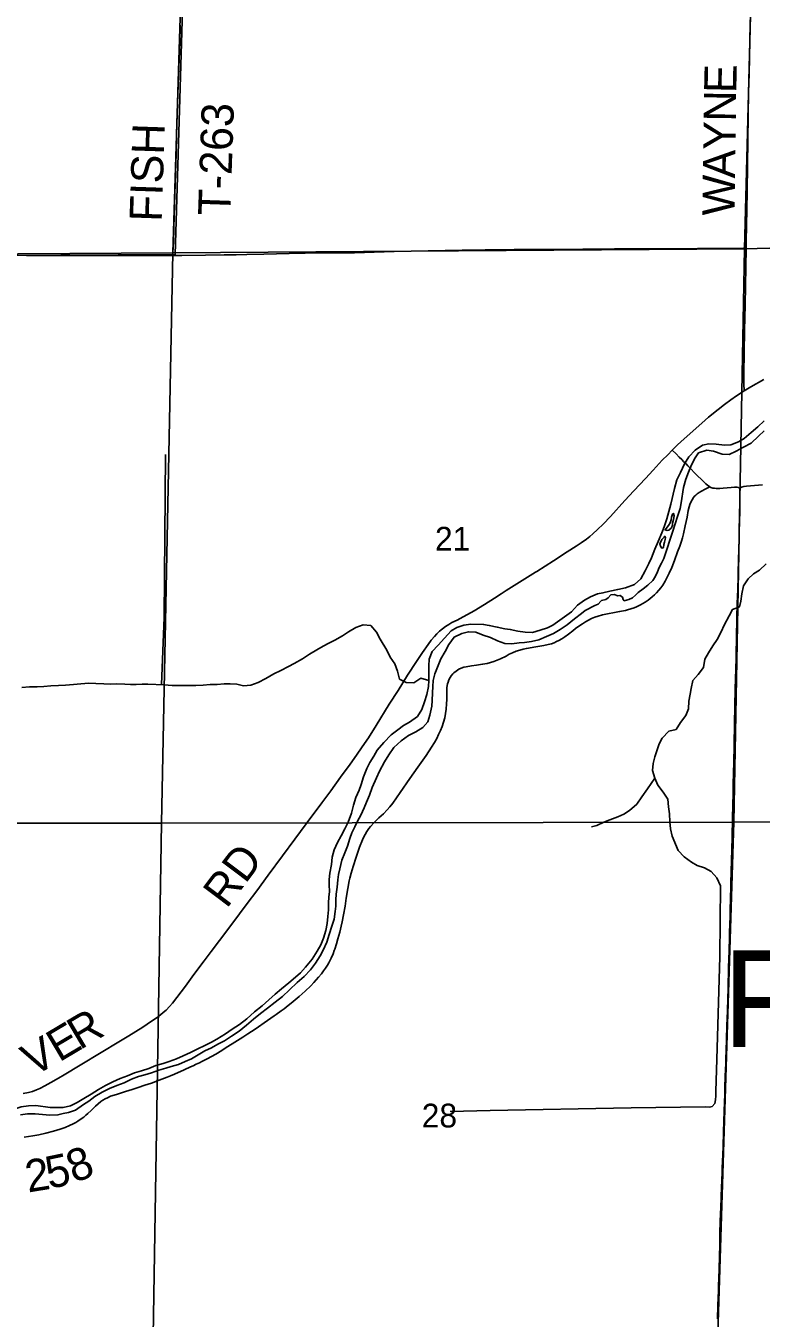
# Model space of a CAD drawing. Extents: x 1443599 to 1910620, y 1028088 to 1361369.
# Drawn here: x 1694297 to 1701141, y 1224516 to 1236539 of the extents above; entities that cross this region are included whole.
import ezdxf

# ---------------------------------------------------------------- set-up
doc = ezdxf.new("R2010")
doc.units = 0
for name, color, linetype in [('GM_X_County_Road', 7, 'Continuous'), ('GM_X_County_Road_Text', 7, 'Continuous'), ('GM_X_Major_River', 7, 'Continuous'), ('GM_X_Minor_River', 7, 'Continuous'), ('GM_X_Section', 7, 'Continuous'), ('GM_X_Section_Text', 7, 'Continuous'), ('GM_X_Township', 7, 'Continuous'), ('GM_X_Township_Road', 7, 'Continuous'), ('GM_X_Township_Road_Text', 7, 'Continuous'), ('GM_X_Township_Text', 7, 'Continuous')]:
    doc.layers.add(name, color=color, linetype=linetype)

msp = doc.modelspace()

# ---------------------------------------------------------------- linework, layer by layer
at = {"layer": 'GM_X_County_Road'}
for points in [[(1700984, 1233144), (1701044, 1233180), (1701165, 1233249)], [(1700314, 1232591), (1700364, 1232642), (1700424, 1232697), (1700590, 1232844), (1700652, 1232898), (1700741, 1232971), (1700799, 1233016), (1700858, 1233060), (1700912, 1233097), (1700974, 1233137), (1700984, 1233144)], [(1694273, 1226605), (1694321, 1226615), (1694359, 1226625), (1694395, 1226639), (1694428, 1226653), (1694475, 1226677), (1694529, 1226707), (1694600, 1226749), (1694653, 1226780), (1694803, 1226870), (1694997, 1226986), (1695162, 1227087), (1695255, 1227143), (1695386, 1227224), (1695468, 1227278), (1695520, 1227313), (1695551, 1227337), (1695576, 1227358), (1695602, 1227382), (1695634, 1227415), (1695662, 1227447), (1695702, 1227498), (1695782, 1227606), (1695860, 1227712), (1695958, 1227840), (1696023, 1227927), (1696101, 1228028), (1696225, 1228194), (1696287, 1228278), (1696358, 1228373), (1696446, 1228492), (1696554, 1228636), (1696686, 1228816), (1696802, 1228971), (1696907, 1229114), (1697052, 1229309), (1697136, 1229423), (1697227, 1229548), (1697316, 1229669), (1697376, 1229755), (1697429, 1229831), (1697485, 1229915), (1697559, 1230031), (1697680, 1230227), (1697762, 1230357), (1697849, 1230497), (1697933, 1230626), (1697988, 1230708), (1698041, 1230783), (1698071, 1230823), (1698100, 1230859), (1698123, 1230883), (1698146, 1230906), (1698174, 1230929), (1698203, 1230951), (1698234, 1230971), (1698263, 1230987), (1698312, 1231011), (1698369, 1231040), (1698409, 1231062), (1698471, 1231098), (1698566, 1231157), (1698658, 1231215), (1698721, 1231255), (1698769, 1231285), (1699041, 1231456), (1699052, 1231463), (1699207, 1231562), (1699337, 1231645), (1699420, 1231699), (1699466, 1231729), (1699517, 1231765), (1699545, 1231787), (1699575, 1231812), (1699619, 1231852), (1699670, 1231903), (1699738, 1231974), (1699873, 1232122), (1699957, 1232213), (1700065, 1232329), (1700136, 1232406), (1700221, 1232497), (1700272, 1232549), (1700314, 1232591)], [(1700663, 1232251), (1700659, 1232253), (1700645, 1232262), (1700626, 1232278), (1700585, 1232318), (1700550, 1232353), (1700459, 1232446), (1700442, 1232464), (1700419, 1232486), (1700402, 1232504), (1700378, 1232527), (1700350, 1232556), (1700314, 1232591)], [(1700939, 1232235), (1700931, 1232243), (1700917, 1232246), (1700910, 1232247), (1700894, 1232247), (1700862, 1232245), (1700789, 1232238), (1700756, 1232236), (1700723, 1232236), (1700706, 1232237), (1700690, 1232239), (1700674, 1232245), (1700663, 1232251)], [(1700734, 1224510), (1700738, 1224633), (1700743, 1224772), (1700744, 1224830), (1700746, 1224879), (1700752, 1225084), (1700755, 1225207), (1700758, 1225313), (1700761, 1225412), (1700764, 1225494), (1700766, 1225543), (1700773, 1225740), (1700775, 1225789), (1700777, 1225879), (1700779, 1225920), (1700781, 1225970), (1700787, 1226109), (1700791, 1226248), (1700794, 1226347), (1700797, 1226437), (1700800, 1226527), (1700802, 1226593), (1700803, 1226668), (1700804, 1226703), (1700806, 1226725), (1700806, 1226767), (1700809, 1226825), (1700812, 1226885), (1700813, 1226923), (1700819, 1227103), (1700823, 1227243), (1700824, 1227300), (1700827, 1227382), (1700833, 1227587), (1700838, 1227776), (1700840, 1227858), (1700842, 1227932), (1700846, 1228063), (1700847, 1228096), (1700850, 1228194), (1700852, 1228243), (1700853, 1228309), (1700857, 1228424), (1700859, 1228530), (1700860, 1228563), (1700863, 1228670), (1700867, 1228875), (1700870, 1228990), (1700874, 1229170), (1700880, 1229400), (1700881, 1229474), (1700884, 1229597), (1700886, 1229679), (1700889, 1229851), (1700894, 1230048), (1700900, 1230368), (1700905, 1230557), (1700908, 1230656), (1700909, 1230697), (1700910, 1230754), (1700911, 1230787), (1700912, 1230860), (1700916, 1231016), (1700919, 1231180), (1700920, 1231213), (1700923, 1231312), (1700926, 1231402), (1700928, 1231459), (1700930, 1231566), (1700933, 1231673), (1700935, 1231763), (1700937, 1231837), (1700938, 1231886), (1700939, 1231935), (1700942, 1232018), (1700944, 1232111), (1700944, 1232146), (1700944, 1232210), (1700943, 1232224), (1700939, 1232235)]]:
    msp.add_lwpolyline(points, dxfattribs=at)
at = {"layer": 'GM_X_Major_River'}
for p, q in [((1700317, 1231893), (1700317, 1231913)), ((1700217, 1231759), (1700202, 1231726))]:
    msp.add_line(p, q, dxfattribs=at)
for points in [[(1701168, 1232864), (1701111, 1232810), (1701048, 1232757), (1700982, 1232701), (1700930, 1232668), (1700859, 1232641), (1700799, 1232637), (1700723, 1232647), (1700653, 1232650), (1700595, 1232638), (1700526, 1232591), (1700468, 1232531), (1700427, 1232464), (1700389, 1232384), (1700357, 1232317), (1700335, 1232235), (1700299, 1232089), (1700283, 1232021), (1700264, 1231952), (1700238, 1231877), (1700217, 1231821), (1700183, 1231742), (1700151, 1231669), (1700121, 1231591), (1700096, 1231538), (1700062, 1231468), (1700020, 1231395), (1699961, 1231341), (1699878, 1231311), (1699806, 1231296), (1699733, 1231280), (1699669, 1231264), (1699619, 1231255), (1699552, 1231226), (1699497, 1231196), (1699432, 1231149), (1699377, 1231088), (1699202, 1230964)], [(1700263, 1231668), (1700293, 1231765), (1700319, 1231837), (1700341, 1231905), (1700363, 1231974), (1700386, 1232050), (1700398, 1232102), (1700417, 1232245), (1700441, 1232323), (1700465, 1232386), (1700492, 1232456), (1700526, 1232519), (1700559, 1232567), (1700634, 1232593), (1700699, 1232581), (1700777, 1232553), (1700843, 1232552), (1700907, 1232582), (1700976, 1232619), (1701047, 1232657), (1701115, 1232723), (1701168, 1232770)], [(1700317, 1231913), (1700324, 1231945), (1700333, 1231981), (1700325, 1232003), (1700315, 1231997), (1700308, 1231967), (1700302, 1231942), (1700293, 1231916), (1700279, 1231892), (1700247, 1231849), (1700265, 1231844), (1700283, 1231848), (1700306, 1231869), (1700317, 1231893)], [(1700202, 1231726), (1700198, 1231718), (1700206, 1231693), (1700217, 1231679), (1700227, 1231683), (1700231, 1231685), (1700236, 1231715), (1700241, 1231735), (1700249, 1231760), (1700252, 1231780), (1700244, 1231791), (1700238, 1231783), (1700217, 1231759)], [(1699334, 1230966), (1699405, 1231021), (1699468, 1231072), (1699503, 1231101), (1699594, 1231145), (1699625, 1231160), (1699649, 1231188), (1699655, 1231192), (1699696, 1231203), (1699718, 1231218), (1699741, 1231244), (1699777, 1231249), (1699804, 1231236), (1699828, 1231240), (1699850, 1231223), (1699858, 1231203), (1699867, 1231191), (1699911, 1231202), (1699944, 1231219), (1699972, 1231242), (1699995, 1231266), (1700044, 1231301), (1700087, 1231334), (1700132, 1231379), (1700155, 1231414), (1700176, 1231458), (1700191, 1231499), (1700214, 1231541), (1700235, 1231584), (1700263, 1231668)], [(1694246, 1226407), (1694314, 1226418), (1694384, 1226417), (1694452, 1226410), (1694520, 1226405), (1694595, 1226407), (1694645, 1226419), (1694695, 1226428), (1694760, 1226451), (1694833, 1226503), (1694882, 1226534), (1694939, 1226579), (1695006, 1226619), (1695076, 1226651), (1695144, 1226680), (1695211, 1226705), (1695280, 1226738), (1695346, 1226765), (1695406, 1226780), (1695467, 1226797), (1695534, 1226824), (1695600, 1226843), (1695650, 1226858), (1695719, 1226877), (1695780, 1226905), (1695840, 1226929), (1695901, 1226965), (1695963, 1227002), (1696024, 1227031), (1696085, 1227064), (1696147, 1227095), (1696212, 1227138), (1696284, 1227185), (1696350, 1227242), (1696415, 1227296), (1696480, 1227351), (1696545, 1227400), (1696618, 1227457), (1696685, 1227508), (1696752, 1227571), (1696824, 1227638), (1696889, 1227695), (1696946, 1227756), (1696993, 1227820), (1697036, 1227887), (1697064, 1227941), (1697098, 1228013), (1697121, 1228085), (1697145, 1228164), (1697166, 1228228), (1697177, 1228300), (1697182, 1228350), (1697183, 1228408), (1697185, 1228459), (1697196, 1228527), (1697201, 1228593), (1697206, 1228643), (1697221, 1228697), (1697238, 1228777), (1697266, 1228844), (1697291, 1228906), (1697314, 1228978), (1697331, 1229030), (1697358, 1229087), (1697385, 1229141), (1697415, 1229195), (1697445, 1229265), (1697467, 1229316), (1697497, 1229382), (1697522, 1229454), (1697562, 1229544), (1697590, 1229605), (1697634, 1229693), (1697675, 1229758), (1697722, 1229824), (1697791, 1229887), (1697858, 1229938), (1697927, 1229971), (1697991, 1230011), (1698038, 1230063), (1698058, 1230127), (1698075, 1230211), (1698080, 1230263), (1698083, 1230333), (1698084, 1230394), (1698089, 1230448), (1698104, 1230509), (1698160, 1230651), (1698199, 1230719), (1698234, 1230784), (1698283, 1230852), (1698354, 1230887), (1698417, 1230902), (1698485, 1230899), (1698555, 1230869)], [(1699202, 1230964), (1699151, 1230940), (1699085, 1230917), (1699014, 1230896), (1698946, 1230897), (1698876, 1230909), (1698806, 1230924), (1698756, 1230929), (1698684, 1230946), (1698610, 1230961), (1698558, 1230970), (1698440, 1230972), (1698375, 1230963), (1698309, 1230943), (1698256, 1230910), (1698195, 1230843), (1698134, 1230778), (1698079, 1230718), (1698050, 1230646), (1698049, 1230585), (1698048, 1230516), (1698048, 1230449), (1698044, 1230392), (1698029, 1230318), (1698009, 1230250), (1697984, 1230179), (1697941, 1230115), (1697868, 1230062), (1697811, 1230029), (1697759, 1229990), (1697698, 1229944), (1697629, 1229873), (1697567, 1229800), (1697536, 1229746), (1697499, 1229685), (1697472, 1229629), (1697441, 1229553), (1697418, 1229482), (1697401, 1229428), (1697370, 1229360), (1697347, 1229290), (1697327, 1229214), (1697296, 1229131), (1697265, 1229067), (1697232, 1229003), (1697199, 1228940), (1697166, 1228874), (1697147, 1228805), (1697142, 1228738), (1697126, 1228656), (1697121, 1228597), (1697119, 1228546), (1697122, 1228484), (1697117, 1228434), (1697114, 1228381), (1697115, 1228315), (1697108, 1228253), (1697103, 1228187), (1697088, 1228121), (1697069, 1228051), (1697044, 1227990), (1697009, 1227930), (1696963, 1227856), (1696900, 1227781), (1696855, 1227730), (1696786, 1227669), (1696744, 1227636), (1696678, 1227581), (1696619, 1227531), (1696558, 1227478), (1696497, 1227421), (1696426, 1227366), (1696355, 1227302), (1696286, 1227249), (1696219, 1227204), (1696156, 1227161), (1696075, 1227112), (1696025, 1227085), (1695962, 1227054), (1695898, 1227021), (1695829, 1226988), (1695760, 1226957), (1695698, 1226928), (1695631, 1226905), (1695575, 1226885), (1695506, 1226867), (1695442, 1226839), (1695375, 1226818), (1695307, 1226799), (1695242, 1226770), (1695175, 1226745), (1695107, 1226716), (1695040, 1226681), (1694973, 1226644), (1694906, 1226601), (1694836, 1226560), (1694775, 1226521), (1694712, 1226491), (1694644, 1226477), (1694576, 1226475), (1694523, 1226475)], [(1698555, 1230869), (1698622, 1230848), (1698688, 1230817), (1698754, 1230794), (1698822, 1230790), (1698888, 1230798), (1698939, 1230803), (1699005, 1230812), (1699073, 1230827), (1699142, 1230858), (1699207, 1230887), (1699271, 1230924), (1699334, 1230966)], [(1694523, 1226475), (1694389, 1226495), (1694321, 1226490), (1694253, 1226481), (1694188, 1226460), (1694124, 1226429), (1694053, 1226396), (1693972, 1226365), (1693913, 1226340), (1693831, 1226313)]]:
    msp.add_lwpolyline(points, dxfattribs=at)
at = {"layer": 'GM_X_Minor_River'}
for points in [[(1695584, 1231034), (1695598, 1232550)], [(1701189, 1231533), (1701126, 1231475), (1701071, 1231442), (1701020, 1231393), (1700976, 1231328), (1700961, 1231254), (1700951, 1231188), (1700940, 1231135), (1700875, 1231110), (1700842, 1231051), (1700798, 1230962)], [(1695560, 1230410), (1695584, 1231034)], [(1698048, 1230449), (1697975, 1230470), (1697908, 1230428), (1697837, 1230430), (1697776, 1230462), (1697756, 1230535), (1697730, 1230604), (1697688, 1230667), (1697658, 1230732), (1697596, 1230834), (1697560, 1230899), (1697508, 1230961), (1697438, 1230965), (1697369, 1230943), (1697299, 1230901), (1697244, 1230864), (1697173, 1230824), (1697116, 1230796), (1697065, 1230767), (1697005, 1230733), (1696938, 1230695), (1696871, 1230651), (1696793, 1230607), (1696742, 1230578), (1696671, 1230542), (1696606, 1230510), (1696532, 1230466), (1696461, 1230430), (1696392, 1230404), (1696324, 1230400), (1696260, 1230414), (1696198, 1230417), (1696144, 1230417), (1696077, 1230411), (1696013, 1230411), (1695947, 1230405), (1695878, 1230403), (1695800, 1230403), (1695724, 1230401), (1695660, 1230403), (1695586, 1230409), (1695431, 1230414), (1695381, 1230413), (1695325, 1230411), (1695271, 1230410), (1695217, 1230414), (1695143, 1230416), (1695082, 1230414), (1695024, 1230417), (1694948, 1230420), (1694882, 1230424), (1694810, 1230418), (1694741, 1230412), (1694667, 1230406), (1694602, 1230402), (1694530, 1230398), (1694466, 1230394), (1694403, 1230389), (1694331, 1230389), (1694261, 1230383)], [(1700798, 1230962), (1700770, 1230900), (1700732, 1230831), (1700692, 1230772), (1700650, 1230707), (1700618, 1230646), (1700604, 1230570), (1700556, 1230503), (1700506, 1230447), (1700490, 1230375), (1700479, 1230321), (1700469, 1230257), (1700465, 1230185), (1700439, 1230124), (1700391, 1230059), (1700349, 1229992), (1700282, 1229976), (1700220, 1229913), (1700192, 1229860), (1700173, 1229804), (1700153, 1229737), (1700137, 1229675), (1700131, 1229611), (1700153, 1229540), (1700179, 1229475), (1700230, 1229410), (1700274, 1229344), (1700278, 1229274), (1700288, 1229209), (1700292, 1229135), (1700296, 1229067), (1700314, 1229000), (1700370, 1228866), (1700423, 1228808), (1700494, 1228758), (1700545, 1228728), (1700615, 1228706), (1700676, 1228670), (1700730, 1228611), (1700762, 1228537)], [(1700153, 1229540), (1700082, 1229440), (1700030, 1229367), (1699984, 1229298), (1699916, 1229238), (1699863, 1229206), (1699808, 1229179), (1699733, 1229151), (1699678, 1229131), (1699613, 1229100), (1699562, 1229086)], [(1700762, 1228537), (1700755, 1227880), (1700728, 1226922), (1700719, 1226629), (1700720, 1226585), (1700715, 1226547), (1700710, 1226513), (1700685, 1226486), (1700661, 1226480), (1700621, 1226483), (1699930, 1226473), (1698619, 1226449), (1698248, 1226438)]]:
    msp.add_lwpolyline(points, dxfattribs=at)
at = {"layer": 'GM_X_Section'}
for points in [[(1695829, 1239703), (1701124, 1239772), (1700987, 1234465), (1695666, 1234426)], [(1701124, 1239772), (1706425, 1239788), (1706263, 1234605), (1700987, 1234465)], [(1695829, 1239703), (1695666, 1234426), (1690385, 1234393), (1690543, 1239680)], [(1706263, 1234605), (1706163, 1229142), (1700887, 1229130), (1700987, 1234465)], [(1690385, 1234393), (1695666, 1234426), (1695560, 1229121), (1690253, 1229120)], [(1700987, 1234465), (1700887, 1229130), (1695560, 1229121), (1695666, 1234426)], [(1690253, 1229120), (1695560, 1229121), (1695473, 1223777), (1690115, 1223779)], [(1695560, 1229121), (1700887, 1229130), (1700722, 1223879), (1695473, 1223777)], [(1700887, 1229130), (1706163, 1229142), (1706163, 1229120), (1706044, 1223810), (1700722, 1223879)]]:
    msp.add_lwpolyline(points, close=True, dxfattribs=at)
at = {"layer": 'GM_X_Township'}
for points in [[(1691028, 1266317), (1696325, 1266276), (1696324, 1260894), (1696308, 1259201), (1696305, 1258547), (1696301, 1258173), (1696288, 1257097), (1696269, 1255587), (1696154, 1250250), (1695980, 1244960), (1695885, 1241542), (1695846, 1239693), (1695686, 1234412), (1693554, 1234401)], [(1693554, 1234401), (1695686, 1234412), (1695846, 1239693)]]:
    msp.add_lwpolyline(points, dxfattribs=at)
at = {"layer": 'GM_X_Township_Road'}
for points in [[(1701001, 1234470), (1701003, 1234534), (1701007, 1234830), (1701010, 1235002), (1701016, 1235478), (1701023, 1235922), (1701028, 1236094), (1701040, 1236554), (1701047, 1236816), (1701057, 1237243), (1701068, 1237785), (1701078, 1238302), (1701081, 1238491), (1701086, 1238737), (1701091, 1239025), (1701094, 1239140), (1701097, 1239255), (1701099, 1239386), (1701101, 1239493), (1701103, 1239608), (1701107, 1239722), (1701107, 1239739), (1701108, 1239773)], [(1695664, 1234402), (1695665, 1234431), (1695670, 1234529), (1695678, 1234776), (1695691, 1235170), (1695695, 1235350), (1695700, 1235531), (1695707, 1235728), (1695719, 1236073), (1695726, 1236303), (1695730, 1236400), (1695731, 1236431), (1695733, 1236496), (1695735, 1236545)], [(1693579, 1234407), (1693679, 1234407), (1694015, 1234406), (1694138, 1234405), (1694303, 1234404), (1694516, 1234404), (1694795, 1234403), (1695197, 1234403), (1695452, 1234402), (1695633, 1234402), (1695664, 1234402)], [(1695664, 1234402), (1695748, 1234402), (1695969, 1234405), (1696142, 1234408), (1696256, 1234410), (1696355, 1234411), (1696511, 1234415), (1696749, 1234420), (1696896, 1234423), (1697119, 1234427), (1697357, 1234429), (1697725, 1234439), (1698357, 1234451), (1698571, 1234454), (1698842, 1234457), (1699145, 1234460), (1699482, 1234462), (1699777, 1234464), (1700319, 1234465), (1700549, 1234467), (1700771, 1234469), (1700976, 1234470), (1701001, 1234470)], [(1700984, 1233144), (1700982, 1233167), (1700980, 1233185), (1700979, 1233221), (1700979, 1233303), (1700986, 1233705), (1700992, 1233943), (1701001, 1234470)], [(1694280, 1226201), (1694321, 1226205), (1694361, 1226211), (1694418, 1226222), (1694482, 1226237), (1694554, 1226256), (1694617, 1226275), (1694663, 1226291), (1694702, 1226307), (1694739, 1226325), (1694761, 1226337), (1694782, 1226349), (1694803, 1226363), (1694836, 1226387), (1694855, 1226403), (1694874, 1226419), (1694904, 1226447), (1694945, 1226487), (1694969, 1226509), (1694994, 1226530), (1695014, 1226544), (1695034, 1226556), (1695056, 1226567), (1695086, 1226580), (1695140, 1226598), (1695225, 1226626), (1695288, 1226644), (1695343, 1226661), (1695405, 1226682), (1695467, 1226703), (1695537, 1226729), (1695613, 1226759), (1695644, 1226771), (1695681, 1226787), (1695772, 1226826), (1695831, 1226854), (1695854, 1226864), (1695883, 1226878), (1695913, 1226892), (1695935, 1226903), (1695986, 1226929), (1696065, 1226973), (1696122, 1227007), (1696163, 1227033), (1696219, 1227068), (1696316, 1227129), (1696364, 1227161), (1696432, 1227206), (1696547, 1227285), (1696608, 1227327), (1696628, 1227342), (1696675, 1227375), (1696701, 1227394), (1696721, 1227409), (1696785, 1227461), (1696841, 1227508), (1696896, 1227558), (1696950, 1227609), (1696978, 1227638), (1697000, 1227663), (1697022, 1227688), (1697048, 1227719), (1697068, 1227746), (1697086, 1227773), (1697104, 1227801), (1697117, 1227822), (1697140, 1227866), (1697157, 1227904), (1697168, 1227935), (1697173, 1227950), (1697189, 1227997), (1697202, 1228045), (1697219, 1228108), (1697232, 1228164), (1697241, 1228204), (1697254, 1228269), (1697268, 1228350), (1697280, 1228423), (1697294, 1228512), (1697307, 1228584), (1697313, 1228608), (1697325, 1228655), (1697343, 1228718), (1697371, 1228804), (1697404, 1228897), (1697430, 1228965), (1697440, 1228988), (1697454, 1229017), (1697470, 1229045), (1697489, 1229072), (1697504, 1229090), (1697538, 1229126), (1697584, 1229172), (1697627, 1229209), (1697659, 1229244), (1697685, 1229274), (1697713, 1229308), (1697781, 1229405), (1697872, 1229537), (1697945, 1229641), (1698023, 1229751), (1698074, 1229829), (1698101, 1229872), (1698122, 1229909), (1698139, 1229945), (1698157, 1229982), (1698171, 1230021), (1698184, 1230061), (1698196, 1230100), (1698202, 1230140), (1698208, 1230181), (1698211, 1230232), (1698214, 1230273), (1698214, 1230289), (1698214, 1230355), (1698215, 1230379), (1698218, 1230403), (1698222, 1230419), (1698227, 1230434), (1698235, 1230456), (1698247, 1230477), (1698256, 1230491), (1698271, 1230509), (1698282, 1230521), (1698301, 1230536), (1698314, 1230545), (1698328, 1230553), (1698350, 1230563), (1698373, 1230571), (1698396, 1230577), (1698444, 1230584), (1698493, 1230590), (1698549, 1230599), (1698590, 1230608), (1698623, 1230616), (1698653, 1230625), (1698684, 1230637), (1698715, 1230650), (1698767, 1230676), (1698796, 1230692), (1698828, 1230707), (1698862, 1230720), (1698894, 1230731), (1698925, 1230741), (1698956, 1230747), (1699045, 1230762), (1699118, 1230774), (1699158, 1230782), (1699190, 1230791), (1699213, 1230800), (1699236, 1230810), (1699259, 1230821), (1699287, 1230837), (1699315, 1230856), (1699348, 1230880), (1699387, 1230911), (1699412, 1230931), (1699444, 1230954), (1699478, 1230977), (1699505, 1230994), (1699534, 1231010), (1699563, 1231024), (1699593, 1231037), (1699624, 1231047), (1699663, 1231058), (1699711, 1231068), (1699775, 1231081), (1699824, 1231089), (1699880, 1231101), (1699896, 1231105), (1699928, 1231114), (1699959, 1231126), (1699981, 1231135), (1700018, 1231154), (1700040, 1231165), (1700061, 1231178), (1700090, 1231196), (1700109, 1231210), (1700128, 1231228), (1700147, 1231245), (1700167, 1231265), (1700189, 1231289), (1700206, 1231310), (1700226, 1231337), (1700247, 1231373), (1700267, 1231409), (1700286, 1231446), (1700309, 1231499), (1700335, 1231566), (1700363, 1231645), (1700384, 1231698), (1700399, 1231744), (1700409, 1231775), (1700419, 1231814), (1700435, 1231886), (1700451, 1231967), (1700462, 1232031), (1700470, 1232063), (1700478, 1232086), (1700487, 1232108), (1700498, 1232130), (1700511, 1232150), (1700521, 1232162), (1700532, 1232174), (1700545, 1232184), (1700564, 1232198), (1700585, 1232211), (1700621, 1232229), (1700663, 1232251)], [(1700939, 1232235), (1700958, 1232248), (1700981, 1232254), (1701006, 1232257), (1701153, 1232268)]]:
    msp.add_lwpolyline(points, dxfattribs=at)

# ---------------------------------------------------------------- texts
at = {"layer": 'GM_X_County_Road_Text'}
for s, rotation, p in [('RD', 53.0322, (1696166, 1228319)), ('E', 30.6821, (1694607, 1226893)), ('R', 30.6197, (1694799, 1227007)), ('V', 28.6549, (1694365, 1226761))]:
    msp.add_text(s, height=300, rotation=rotation, dxfattribs=at).set_placement(p)
at = {"layer": 'GM_X_Section_Text'}
for s, p in [('21', (1698105, 1231657)), ('28', (1697982, 1226290))]:
    msp.add_text(s, height=221, rotation=0, dxfattribs=at).set_placement(p)
at = {"layer": 'GM_X_Township_Road_Text'}
for s, rotation, p in [('E', 88.6628, (1700909, 1235911)), ('T-263', 88.0353, (1696199, 1234770)), ('N', 89.2168, (1700905, 1235647)), ('FISH', 88.0975, (1695561, 1234714)), ('Y', 89.2313, (1700902, 1235383)), ('A', 89.235, (1700898, 1235119)), ('W', 89.2336, (1700893, 1234772)), ('8', 21.2554, (1694747, 1225770)), ('2', 9.2368, (1694317, 1225684)), ('5', 11.8041, (1694514, 1225717))]:
    msp.add_text(s, height=300, rotation=rotation, dxfattribs=at).set_placement(p)
at = {"layer": 'GM_X_Township_Text'}
msp.add_text('FREEDOM', height=900, rotation=0, dxfattribs=at).set_placement((1700784, 1227038))

doc.saveas('drawing.dxf')
